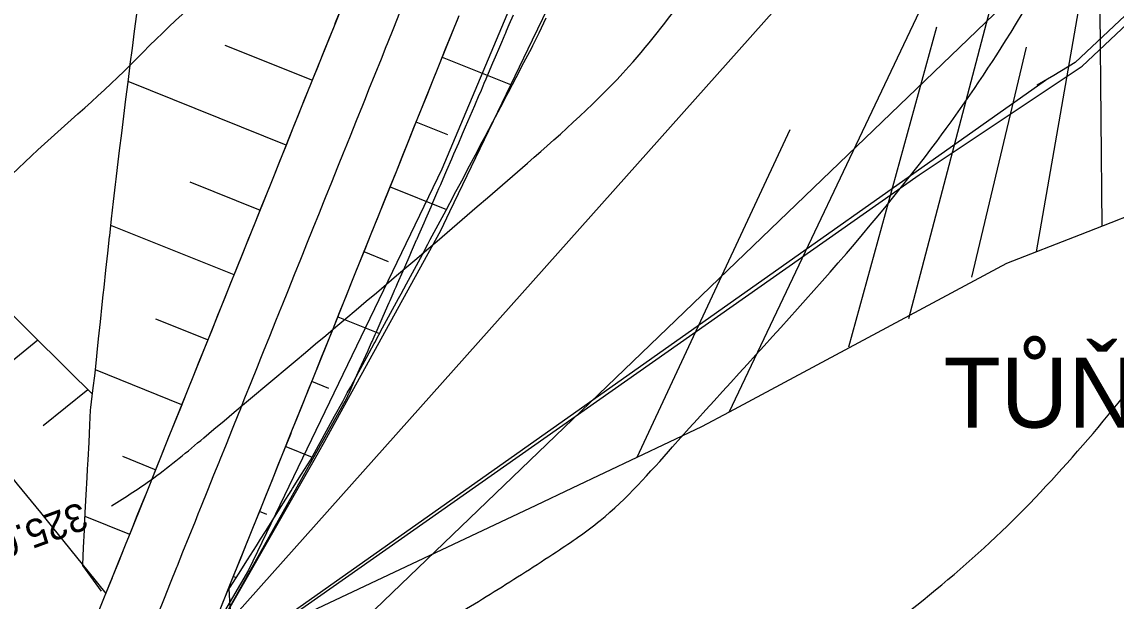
# Model space of a CAD drawing. Extents: x -564037 to -563827, y -1163561 to -1163412.
# Drawn here: x -563980.78 to -563961.22, y -1163500.71 to -1163490.36 of the extents above; entities that cross this region are included whole.
import ezdxf

# ---------------------------------------------------------------- set-up
doc = ezdxf.new("R2010")
doc.units = 0
for name, color, linetype in [('4', 7, 'Continuous'), ('5', 7, 'Continuous'), ('Default', 7, 'Continuous'), ('Line', 7, 'Continuous'), ('Vrstva 24', 7, 'Continuous'), ('Vrstva 25', 7, 'Continuous'), ('Vrstva 26', 7, 'Continuous')]:
    doc.layers.add(name, color=color, linetype=linetype)

msp = doc.modelspace()

# ---------------------------------------------------------------- linework, layer by layer
msp.add_lwpolyline([(-563976.663, -1163501.462), (-563964.742, -1163493.091), (-563961.829, -1163491.15), (-563957.41, -1163486.988), (-563956.735, -1163486.627), (-563953.281, -1163481.221), (-563953.993, -1163478.343), (-563957.796, -1163470.824), (-563957.81, -1163470.439), (-563957.835, -1163469.754), (-563958.239, -1163469.063), (-563958.187, -1163468.683), (-563959.529, -1163466.077), (-563960.166, -1163464.984), (-563964.31, -1163473.527), (-563966.903, -1163478.544), (-563968.406, -1163481.669), (-563970.316, -1163485.955), (-563973.278, -1163492.988), (-563976.735, -1163500.155), (-563977.161, -1163500.889), (-563977.363, -1163501.307)], close=True)
for points in [[(-563960.591, -1163493.664), (-563961.319, -1163493.948), (-563961.866, -1163494.161), (-563963.182, -1163494.674), (-563968.138, -1163497.33), (-563968.634, -1163497.596), (-563970.944, -1163498.688), (-563971.597, -1163498.997), (-563976.56, -1163501.343), (-563977.332, -1163501.295), (-563976.988, -1163500.693), (-563975.559, -1163498.192), (-563975.396, -1163497.906), (-563973.296, -1163494.084), (-563973.133, -1163493.747), (-563971.654, -1163490.682), (-563969.513, -1163486.248), (-563968.702, -1163484.611), (-563968.142, -1163483.478), (-563966.349, -1163479.855)], [(-563979.277, -1163500.562), (-563978.932, -1163499.705), (-563978.872, -1163499.557), (-563978.558, -1163498.777), (-563978.185, -1163497.849), (-563977.812, -1163496.922), (-563977.438, -1163495.994), (-563977.065, -1163495.066), (-563976.691, -1163494.139), (-563976.318, -1163493.211), (-563975.945, -1163492.283), (-563975.571, -1163491.355), (-563975.198, -1163490.428), (-563974.825, -1163489.5)], [(-563979.678, -1163501.56), (-563979.305, -1163500.632), (-563979.277, -1163500.562), (-563979.165, -1163500.284), (-563979.164, -1163500.282), (-563979.053, -1163500.006), (-563978.942, -1163499.731), (-563978.932, -1163499.705), (-563978.832, -1163499.456), (-563978.721, -1163499.18), (-563978.61, -1163498.905), (-563978.558, -1163498.777), (-563978.499, -1163498.63), (-563978.388, -1163498.355), (-563978.277, -1163498.079), (-563978.185, -1163497.849), (-563978.167, -1163497.804), (-563978.056, -1163497.529), (-563977.945, -1163497.253), (-563977.834, -1163496.978), (-563977.812, -1163496.922), (-563977.723, -1163496.703), (-563977.613, -1163496.427), (-563977.502, -1163496.152), (-563977.438, -1163495.994), (-563977.391, -1163495.877), (-563977.28, -1163495.601), (-563977.169, -1163495.326), (-563977.065, -1163495.066), (-563977.059, -1163495.051), (-563976.948, -1163494.775), (-563976.837, -1163494.5), (-563976.726, -1163494.225), (-563976.691, -1163494.139), (-563976.615, -1163493.949), (-563976.505, -1163493.674), (-563976.394, -1163493.399), (-563976.318, -1163493.211), (-563976.283, -1163493.123), (-563976.172, -1163492.848), (-563976.061, -1163492.573), (-563975.95, -1163492.297), (-563975.945, -1163492.283), (-563975.84, -1163492.022), (-563975.729, -1163491.747), (-563975.618, -1163491.471), (-563975.571, -1163491.355), (-563975.507, -1163491.196), (-563975.396, -1163490.921), (-563975.286, -1163490.645), (-563975.198, -1163490.428), (-563975.175, -1163490.37), (-563975.064, -1163490.095)], [(-563979.359, -1163500.529), (-563979.695, -1163500.07), (-563979.695, -1163500.068), (-563979.682, -1163499.753), (-563979.667, -1163499.439), (-563979.666, -1163499.409), (-563979.652, -1163499.126), (-563979.635, -1163498.812), (-563979.619, -1163498.499), (-563979.611, -1163498.353), (-563979.602, -1163498.186), (-563979.584, -1163497.873), (-563979.571, -1163497.559), (-563979.558, -1163497.297), (-563979.551, -1163497.247), (-563979.514, -1163496.942), (-563979.476, -1163496.637), (-563979.444, -1163496.33), (-563979.438, -1163496.267), (-563979.413, -1163496.023), (-563979.381, -1163495.716), (-563979.348, -1163495.409), (-563979.33, -1163495.233), (-563979.316, -1163495.102), (-563979.282, -1163494.796), (-563979.248, -1163494.489), (-563979.216, -1163494.2), (-563979.214, -1163494.183), (-563979.18, -1163493.877), (-563979.145, -1163493.571), (-563979.109, -1163493.266), (-563979.098, -1163493.17), (-563979.073, -1163492.96), (-563979.037, -1163492.655), (-563979, -1163492.35), (-563978.975, -1163492.142), (-563978.963, -1163492.045), (-563978.925, -1163491.74), (-563978.887, -1163491.435), (-563978.848, -1163491.131), (-563978.846, -1163491.115), (-563978.809, -1163490.827), (-563978.77, -1163490.523), (-563978.73, -1163490.219)], [(-563979.359, -1163500.529), (-563979.695, -1163500.07), (-563979.695, -1163500.068), (-563979.682, -1163499.753), (-563979.667, -1163499.439), (-563979.666, -1163499.409), (-563979.652, -1163499.126), (-563979.635, -1163498.812), (-563979.619, -1163498.499), (-563979.611, -1163498.353), (-563979.602, -1163498.186), (-563979.584, -1163497.873), (-563979.571, -1163497.559), (-563979.558, -1163497.297), (-563979.551, -1163497.247), (-563979.514, -1163496.942), (-563979.476, -1163496.637), (-563979.444, -1163496.33), (-563979.438, -1163496.267), (-563979.413, -1163496.023), (-563979.381, -1163495.716), (-563979.348, -1163495.409), (-563979.33, -1163495.233), (-563979.316, -1163495.102), (-563979.282, -1163494.796), (-563979.248, -1163494.489), (-563979.216, -1163494.2), (-563979.214, -1163494.183), (-563979.18, -1163493.877), (-563979.145, -1163493.571), (-563979.109, -1163493.266), (-563979.098, -1163493.17), (-563979.073, -1163492.96), (-563979.037, -1163492.655), (-563979, -1163492.35), (-563978.975, -1163492.142), (-563978.963, -1163492.045), (-563978.925, -1163491.74), (-563978.887, -1163491.435), (-563978.848, -1163491.131), (-563978.846, -1163491.115), (-563978.809, -1163490.827), (-563978.77, -1163490.523), (-563978.73, -1163490.219)], [(-563978.349, -1163500.935), (-563978.237, -1163500.657), (-563978.236, -1163500.655), (-563978.125, -1163500.38), (-563978.015, -1163500.104), (-563978.004, -1163500.078), (-563977.904, -1163499.829), (-563977.793, -1163499.554), (-563977.682, -1163499.279), (-563977.631, -1163499.15), (-563977.571, -1163499.003), (-563977.461, -1163498.728), (-563977.35, -1163498.453), (-563977.257, -1163498.223), (-563977.239, -1163498.177), (-563977.128, -1163497.902), (-563977.017, -1163497.627), (-563976.907, -1163497.351), (-563976.884, -1163497.295), (-563976.796, -1163497.076), (-563976.685, -1163496.801), (-563976.574, -1163496.525), (-563976.511, -1163496.367), (-563976.463, -1163496.25), (-563976.353, -1163495.975), (-563976.242, -1163495.699), (-563976.137, -1163495.44), (-563976.131, -1163495.424), (-563976.02, -1163495.149), (-563975.909, -1163494.873), (-563975.798, -1163494.598), (-563975.764, -1163494.512), (-563975.688, -1163494.323), (-563975.577, -1163494.047), (-563975.466, -1163493.772), (-563975.39, -1163493.584), (-563975.355, -1163493.497), (-563975.244, -1163493.221), (-563975.134, -1163492.946), (-563975.023, -1163492.671), (-563975.017, -1163492.657), (-563974.912, -1163492.395), (-563974.801, -1163492.12), (-563974.69, -1163491.845), (-563974.644, -1163491.729), (-563974.58, -1163491.569), (-563974.469, -1163491.294), (-563974.358, -1163491.019), (-563974.27, -1163490.801), (-563974.247, -1163490.744), (-563974.136, -1163490.468), (-563974.025, -1163490.193)], [(-563977.421, -1163501.309), (-563977.076, -1163500.451), (-563977.017, -1163500.304), (-563976.703, -1163499.524), (-563976.33, -1163498.596), (-563975.956, -1163497.668), (-563975.583, -1163496.741), (-563975.209, -1163495.813), (-563974.836, -1163494.885), (-563974.463, -1163493.958), (-563974.089, -1163493.03), (-563973.716, -1163492.102), (-563973.343, -1163491.175), (-563972.969, -1163490.247)], [(-563977.198, -1163500.753), (-563977.087, -1163500.478), (-563977.076, -1163500.451), (-563976.976, -1163500.203), (-563976.865, -1163499.927), (-563976.755, -1163499.652), (-563976.703, -1163499.524), (-563976.644, -1163499.377), (-563976.533, -1163499.101), (-563976.422, -1163498.826), (-563976.33, -1163498.596), (-563976.311, -1163498.551), (-563976.201, -1163498.275), (-563976.09, -1163498), (-563975.979, -1163497.725), (-563975.956, -1163497.668), (-563975.868, -1163497.449), (-563975.757, -1163497.174), (-563975.646, -1163496.899), (-563975.583, -1163496.741), (-563975.536, -1163496.623), (-563975.425, -1163496.348), (-563975.314, -1163496.073), (-563975.209, -1163495.813), (-563975.203, -1163495.797), (-563975.092, -1163495.522), (-563974.982, -1163495.247), (-563974.871, -1163494.971), (-563974.836, -1163494.885), (-563974.76, -1163494.696), (-563974.649, -1163494.421), (-563974.538, -1163494.145), (-563974.463, -1163493.958), (-563974.428, -1163493.87), (-563974.317, -1163493.595), (-563974.206, -1163493.319), (-563974.095, -1163493.044), (-563974.089, -1163493.03), (-563973.984, -1163492.769), (-563973.873, -1163492.493), (-563973.763, -1163492.218), (-563973.716, -1163492.102), (-563973.652, -1163491.943), (-563973.541, -1163491.668), (-563973.43, -1163491.392), (-563973.343, -1163491.175), (-563973.319, -1163491.117), (-563973.209, -1163490.842), (-563973.098, -1163490.566), (-563972.987, -1163490.291)], [(-563977.077, -1163500.482), (-563977.061, -1163500.458), (-563976.914, -1163500.227), (-563976.753, -1163499.973), (-563976.591, -1163499.718), (-563976.516, -1163499.599), (-563976.429, -1163499.463), (-563976.268, -1163499.208), (-563976.107, -1163498.953), (-563975.973, -1163498.74), (-563975.946, -1163498.698), (-563975.785, -1163498.442), (-563975.625, -1163498.187), (-563975.48, -1163497.925), (-563975.451, -1163497.872), (-563975.336, -1163497.663), (-563975.193, -1163497.401), (-563975.049, -1163497.139), (-563974.967, -1163496.989), (-563974.906, -1163496.877), (-563974.763, -1163496.614), (-563974.62, -1163496.352), (-563974.485, -1163496.104), (-563974.477, -1163496.09), (-563974.335, -1163495.827), (-563974.192, -1163495.564), (-563974.05, -1163495.302), (-563974.006, -1163495.219), (-563973.909, -1163495.039), (-563973.767, -1163494.776), (-563973.625, -1163494.513), (-563973.529, -1163494.333), (-563973.484, -1163494.25), (-563973.343, -1163493.987), (-563973.202, -1163493.723), (-563973.062, -1163493.46), (-563973.055, -1163493.446), (-563972.922, -1163493.196), (-563972.782, -1163492.933), (-563972.642, -1163492.669), (-563972.583, -1163492.558), (-563972.502, -1163492.405), (-563972.363, -1163492.142), (-563972.224, -1163491.878), (-563972.114, -1163491.669), (-563972.085, -1163491.614), (-563971.946, -1163491.35), (-563971.808, -1163491.085), (-563971.669, -1163490.821), (-563971.647, -1163490.779), (-563971.537, -1163490.555), (-563971.41, -1163490.286)], [(-563977.077, -1163500.482), (-563977.061, -1163500.458), (-563976.914, -1163500.227), (-563976.753, -1163499.973), (-563976.591, -1163499.718), (-563976.516, -1163499.599), (-563976.429, -1163499.463), (-563976.268, -1163499.208), (-563976.107, -1163498.953), (-563975.973, -1163498.74), (-563975.946, -1163498.698), (-563975.785, -1163498.442), (-563975.625, -1163498.187), (-563975.48, -1163497.925), (-563975.451, -1163497.872), (-563975.336, -1163497.663), (-563975.193, -1163497.401), (-563975.049, -1163497.139), (-563974.967, -1163496.989), (-563974.906, -1163496.877), (-563974.763, -1163496.614), (-563974.62, -1163496.352), (-563974.485, -1163496.104), (-563974.477, -1163496.09), (-563974.335, -1163495.827), (-563974.192, -1163495.564), (-563974.05, -1163495.302), (-563974.006, -1163495.219), (-563973.909, -1163495.039), (-563973.767, -1163494.776), (-563973.625, -1163494.513), (-563973.529, -1163494.333), (-563973.484, -1163494.25), (-563973.343, -1163493.987), (-563973.202, -1163493.723), (-563973.062, -1163493.46), (-563973.055, -1163493.446), (-563972.922, -1163493.196), (-563972.782, -1163492.933), (-563972.642, -1163492.669), (-563972.583, -1163492.558), (-563972.502, -1163492.405), (-563972.363, -1163492.142), (-563972.224, -1163491.878), (-563972.114, -1163491.669), (-563972.085, -1163491.614), (-563971.946, -1163491.35), (-563971.808, -1163491.085), (-563971.669, -1163490.821), (-563971.647, -1163490.779), (-563971.537, -1163490.555), (-563971.41, -1163490.286)], [(-563986.706, -1163491.418), (-563986.045, -1163492.234), (-563985.906, -1163492.405), (-563985.276, -1163493.181), (-563985.14, -1163493.35), (-563984.646, -1163493.958), (-563984.016, -1163494.734), (-563983.386, -1163495.511), (-563982.756, -1163496.288), (-563982.126, -1163497.064), (-563981.496, -1163497.841), (-563980.866, -1163498.617), (-563980.454, -1163499.125), (-563980.236, -1163499.394), (-563979.606, -1163500.17), (-563979.281, -1163500.571)], [(-563984.543, -1163491.913), (-563984.084, -1163492.493), (-563983.524, -1163493.048), (-563982.81, -1163493.756), (-563982.095, -1163494.463), (-563981.38, -1163495.171), (-563980.665, -1163495.879), (-563979.951, -1163496.587), (-563979.523, -1163497.011)], [(-563979.198, -1163507.467), (-563978.368, -1163507.477), (-563975.597, -1163507.515), (-563975.386, -1163507.517), (-563975.87, -1163506.327), (-563976.036, -1163505.182), (-563976.046, -1163504.1), (-563976.056, -1163503.018), (-563976.088, -1163501.927), (-563976.1, -1163501.84), (-563976.996, -1163501.156), (-563976.997, -1163501.154), (-563977.062, -1163500.808), (-563977.077, -1163500.482)], [(-563979.198, -1163507.467), (-563978.368, -1163507.477), (-563975.597, -1163507.515), (-563975.386, -1163507.517), (-563975.87, -1163506.327), (-563976.036, -1163505.182), (-563976.046, -1163504.1), (-563976.056, -1163503.018), (-563976.088, -1163501.927), (-563976.1, -1163501.84), (-563976.996, -1163501.156), (-563976.997, -1163501.154), (-563977.062, -1163500.808), (-563977.077, -1163500.482)]]:
    msp.add_lwpolyline(points)
at = {"layer": '5'}
msp.add_line((-563974.94, -1163501.303), (-563959.546, -1163486.507), dxfattribs=at)
at = {"layer": 'Default'}
for points in [[(-563957.497, -1163486.891), (-563961.953, -1163491.085), (-563962.333, -1163491.316), (-563962.631, -1163491.492), (-563962.482, -1163491.404), (-563976.56, -1163501.343)], [(-563977.332, -1163501.295), (-563974.976, -1163497.082), (-563974.974, -1163497.079), (-563974.939, -1163497), (-563974.935, -1163496.992), (-563974.849, -1163496.797), (-563974.841, -1163496.78), (-563974.722, -1163496.513), (-563974.711, -1163496.488), (-563974.596, -1163496.229), (-563974.589, -1163496.212), (-563974.532, -1163496.085), (-563974.525, -1163496.068), (-563974.47, -1163495.944), (-563974.453, -1163495.906), (-563974.344, -1163495.659), (-563974.324, -1163495.615), (-563974.218, -1163495.374), (-563974.203, -1163495.339), (-563974.128, -1163495.17), (-563974.122, -1163495.155), (-563974.093, -1163495.09), (-563974.069, -1163495.034), (-563973.968, -1163494.805), (-563973.941, -1163494.744), (-563973.843, -1163494.52), (-563973.816, -1163494.459), (-563973.727, -1163494.254), (-563973.725, -1163494.249), (-563973.718, -1163494.234), (-563973.688, -1163494.165), (-563973.594, -1163493.949), (-563973.562, -1163493.876), (-563973.47, -1163493.664), (-563973.436, -1163493.586), (-563973.346, -1163493.378), (-563973.341, -1163493.366), (-563973.328, -1163493.337), (-563973.297, -1163493.267), (-563973.222, -1163493.093), (-563973.185, -1163493.008), (-563973.099, -1163492.807), (-563973.061, -1163492.719), (-563972.975, -1163492.522), (-563972.961, -1163492.488), (-563972.931, -1163492.418), (-563972.905, -1163492.359), (-563972.852, -1163492.236), (-563972.812, -1163492.141), (-563972.729, -1163491.95), (-563972.688, -1163491.852), (-563972.607, -1163491.664), (-563972.582, -1163491.606), (-563972.536, -1163491.499), (-563972.518, -1163491.456), (-563972.485, -1163491.378), (-563972.441, -1163491.275), (-563972.363, -1163491.092), (-563972.318, -1163490.986), (-563972.241, -1163490.805), (-563972.204, -1163490.719), (-563972.145, -1163490.579), (-563972.135, -1163490.556), (-563972.119, -1163490.519), (-563972.072, -1163490.408), (-563971.998, -1163490.232)]]:
    msp.add_lwpolyline(points, dxfattribs=at)
at = {"layer": 'Line'}
for p, q in [((-563962.901, -1163485.181), (-563977.279, -1163501.298)), ((-563964.928, -1163495.656), (-563962.285, -1163485.606)), ((-563968.138, -1163497.33), (-563962.69, -1163485.858)), ((-563962.645, -1163494.465), (-563961.176, -1163486.037)), ((-563961.513, -1163490.172), (-563961.48, -1163494.011)), ((-563964.431, -1163490.456), (-563966.005, -1163496.172)), ((-563977.155, -1163490.772), (-563975.59, -1163491.402)), ((-563962.83, -1163490.808), (-563963.81, -1163494.918)), ((-563973.268, -1163490.989), (-563972.021, -1163491.491)), ((-563976.057, -1163492.562), (-563978.885, -1163491.423)), ((-563973.171, -1163492.376), (-563973.735, -1163492.149)), ((-563967.053, -1163492.285), (-563969.789, -1163498.142)), ((-563977.783, -1163493.214), (-563976.523, -1163493.721)), ((-563974.201, -1163493.308), (-563973.196, -1163493.713)), ((-563976.99, -1163494.881), (-563979.193, -1163493.994)), ((-563974.23, -1163494.644), (-563974.668, -1163494.468)), ((-563978.396, -1163495.662), (-563977.457, -1163496.04)), ((-563975.135, -1163495.627), (-563974.389, -1163495.928)), ((-563981.981, -1163497.243), (-563980.501, -1163496.042)), ((-563977.924, -1163497.2), (-563979.47, -1163496.578)), ((-563975.296, -1163496.91), (-563975.602, -1163496.787)), ((-563980.401, -1163497.57), (-563979.608, -1163496.927)), ((-563976.068, -1163497.947), (-563975.597, -1163498.136)), ((-563978.988, -1163498.119), (-563978.39, -1163498.36)), ((-563976.403, -1163499.159), (-563976.535, -1163499.106)), ((-563978.857, -1163499.519), (-563979.655, -1163499.198)), ((-563977.002, -1163500.266), (-563976.952, -1163500.286))]:
    msp.add_line(p, q, dxfattribs=at)
at = {"layer": 'Vrstva 24'}
for points in [[(-563987.107, -1163486.915), (-563987.454, -1163489.613), (-563987.517, -1163490.15), (-563987.54, -1163490.422), (-563987.53, -1163490.559), (-563987.493, -1163490.695), (-563987.417, -1163490.784), (-563987.298, -1163490.832), (-563987.065, -1163490.801), (-563986.897, -1163490.636), (-563986.866, -1163490.616), (-563986.653, -1163490.561), (-563986.65, -1163490.24), (-563986.645, -1163490.2), (-563986.382, -1163489.381), (-563986.092, -1163488.576), (-563985.799, -1163487.775), (-563985.528, -1163486.967), (-563985.38, -1163486.476), (-563984.961, -1163484.997), (-563984.678, -1163484.011), (-563984.372, -1163483.032), (-563984.225, -1163482.649), (-563983.962, -1163482.075), (-563983.672, -1163481.512), (-563983.189, -1163480.348), (-563983.119, -1163479.959), (-563982.881, -1163478.598), (-563982.738, -1163477.921), (-563982.65, -1163477.583), (-563982.6, -1163477.415), (-563982.546, -1163477.247), (-563982.332, -1163477.109), (-563982.215, -1163477.074), (-563982.092, -1163477.059), (-563981.971, -1163477.035), (-563981.858, -1163476.974), (-563981.222, -1163476.317), (-563980.763, -1163475.576), (-563980.303, -1163473.933), (-563980.283, -1163473.505), (-563980.299, -1163473.076), (-563980.318, -1163472.648), (-563980.308, -1163472.221), (-563980.208, -1163471.241), (-563979.978, -1163470.27), (-563979.506, -1163469.655), (-563979.053, -1163469.383), (-563978.331, -1163469.068), (-563977.756, -1163469.029), (-563977.053, -1163469.053), (-563976.495, -1163468.977), (-563976.227, -1163468.861), (-563976.095, -1163468.775), (-563975.963, -1163468.666), (-563975.645, -1163468.239), (-563975.569, -1163468.015), (-563975.54, -1163467.788), (-563975.712, -1163467.263), (-563975.92, -1163467.014), (-563976.134, -1163466.799), (-563976.603, -1163466.431), (-563977.767, -1163465.694), (-563978.114, -1163465.416), (-563978.319, -1163465.046), (-563978.354, -1163464.593), (-563978.366, -1163464.139), (-563978.374, -1163463.685), (-563978.396, -1163463.232), (-563978.403, -1163463.165), (-563978.508, -1163462.771), (-563978.665, -1163462.394), (-563979.088, -1163461.691), (-563979.473, -1163461.171), (-563980.119, -1163460.346)], [(-563978.297, -1163509.021), (-563978.261, -1163509.003), (-563973.613, -1163506.565), (-563973.263, -1163506.351), (-563972.852, -1163506.074), (-563964.784, -1163500.778), (-563963.064, -1163499.262), (-563960.133, -1163495.845), (-563958.857, -1163494.133), (-563956.661, -1163490.461), (-563954.703, -1163486.917), (-563951.017, -1163480.396), (-563950.659, -1163479.782), (-563950.563, -1163479.619)], [(-563978.949, -1163516.619), (-563975.171, -1163515.313), (-563974.108, -1163514.884), (-563972.002, -1163513.885), (-563969.907, -1163512.865), (-563967.813, -1163511.846), (-563965.709, -1163510.847), (-563964.325, -1163510.207), (-563962.597, -1163509.381), (-563961.075, -1163508.613), (-563959.57, -1163507.812), (-563958.075, -1163506.99), (-563956.583, -1163506.159), (-563955.558, -1163505.578), (-563954.547, -1163504.976), (-563953.555, -1163504.342), (-563952.588, -1163503.665), (-563951.319, -1163502.66), (-563950.112, -1163501.587), (-563949.038, -1163500.583), (-563947.98, -1163499.563), (-563946.918, -1163498.547), (-563945.835, -1163497.554), (-563945.703, -1163497.443), (-563945.609, -1163497.371), (-563945.171, -1163496.955), (-563943.72, -1163495.5)]]:
    msp.add_spline(points, degree=3, dxfattribs=at)
at = {"layer": 'Vrstva 25'}
msp.add_spline([(-563979.181, -1163499.008), (-563978.428, -1163498.506), (-563977.533, -1163497.79), (-563971.745, -1163492.882), (-563969.933, -1163491.157), (-563968.824, -1163489.747), (-563966.163, -1163485.494), (-563965.399, -1163484.181), (-563964.1, -1163481.868), (-563961.431, -1163477.021), (-563960.731, -1163475.725), (-563960.044, -1163474.189), (-563959.617, -1163472.641), (-563959.116, -1163469.866), (-563959.228, -1163469.046), (-563959.512, -1163468.326), (-563959.82, -1163467.638), (-563960.515, -1163466.313), (-563961.208, -1163465.1)], degree=3, dxfattribs=at)
at = {"layer": 'Vrstva 26'}
for points in [[(-563980.746, -1163506.255), (-563980.047, -1163505.928), (-563978.898, -1163505.186), (-563978.091, -1163504.559), (-563977.304, -1163503.908), (-563976.514, -1163503.264), (-563975.695, -1163502.656), (-563974.591, -1163501.929), (-563973.468, -1163501.232), (-563972.341, -1163500.538), (-563971.226, -1163499.825), (-563970.447, -1163499.268), (-563969.15, -1163497.951), (-563964.517, -1163492.611), (-563963.2, -1163490.7), (-563960.284, -1163485.41), (-563958.779, -1163482.786), (-563956.142, -1163478.307), (-563954.428, -1163475.228)], [(-563991.611, -1163485.501), (-563991.561, -1163485.341), (-563991.21, -1163484.328), (-563991.006, -1163483.823), (-563990.782, -1163483.317), (-563990.669, -1163483.212), (-563989.835, -1163483.385), (-563989.335, -1163483.591), (-563988.852, -1163483.806), (-563988.416, -1163484.095), (-563988.226, -1163484.288), (-563988.06, -1163484.524), (-563987.844, -1163485.266), (-563987.9, -1163486.009), (-563988.137, -1163487.627), (-563988.511, -1163490.277), (-563988.935, -1163493.479), (-563989.128, -1163493.944), (-563989.201, -1163494.071), (-563989.25, -1163494.355), (-563988.964, -1163494.223), (-563988.759, -1163494.176), (-563988.506, -1163494.004), (-563988.295, -1163493.783), (-563987.947, -1163493.254), (-563987.614, -1163492.703), (-563987.194, -1163492.246), (-563986.965, -1163492.108), (-563986.555, -1163492.017), (-563986.094, -1163492.011), (-563985.68, -1163491.951), (-563985.522, -1163491.857), (-563985.413, -1163491.697), (-563985.286, -1163491.116), (-563985.31, -1163490.532), (-563985.383, -1163489.947), (-563985.403, -1163489.364), (-563985.38, -1163489.09), (-563984.85, -1163487.266), (-563984.13, -1163485.089), (-563983.855, -1163484.492), (-563982.893, -1163482.465), (-563982.427, -1163481.437), (-563982.206, -1163480.907), (-563982.1, -1163480.637), (-563981.997, -1163480.363), (-563981.967, -1163480.031), (-563981.995, -1163479.694), (-563982.002, -1163479.122), (-563981.99, -1163478.836), (-563981.972, -1163478.693), (-563981.942, -1163478.551), (-563981.849, -1163478.489), (-563981.662, -1163478.435), (-563981.467, -1163478.411), (-563981.273, -1163478.37), (-563981.089, -1163478.263), (-563980.515, -1163477.708), (-563980.017, -1163477.13), (-563979.334, -1163476.087)], [(-564001.195, -1163498.271), (-563999.625, -1163497.54), (-563999.32, -1163497.49), (-563999.014, -1163497.455), (-563998.404, -1163497.374), (-563997.456, -1163497.19), (-563996.983, -1163497.106), (-563996.746, -1163497.08), (-563996.628, -1163497.073), (-563996.51, -1163497.07), (-563996.001, -1163497.405), (-563995.843, -1163497.69), (-563995.811, -1163497.929), (-563995.865, -1163498.008), (-563995.966, -1163498.084), (-563996.177, -1163498.245), (-563996.314, -1163498.396), (-563996.473, -1163498.559), (-563996.786, -1163498.911), (-563996.954, -1163499.618), (-563996.725, -1163499.926), (-563996.435, -1163500.208), (-563996.113, -1163500.428), (-563995.791, -1163500.55), (-563995.579, -1163500.527), (-563995.362, -1163500.405), (-563995.147, -1163500.225), (-563994.94, -1163500.032), (-563994.454, -1163499.316), (-563994.189, -1163498.497), (-563993.911, -1163497.703), (-563993.694, -1163497.356), (-563993.385, -1163497.063), (-563993.106, -1163496.925), (-563992.801, -1163496.863), (-563992.211, -1163496.877), (-563991.901, -1163497.039), (-563991.591, -1163497.33), (-563991.287, -1163497.564), (-563990.995, -1163497.556), (-563990.269, -1163497.037), (-563989.554, -1163496.504), (-563988.84, -1163495.969), (-563988.119, -1163495.444), (-563987.86, -1163495.24), (-563987.725, -1163495.146), (-563987.573, -1163495.071), (-563987.369, -1163495.063), (-563987.165, -1163495.092), (-563986.561, -1163495.087), (-563985.951, -1163495.108), (-563984.727, -1163495.135), (-563983.531, -1163494.982), (-563982.954, -1163494.778), (-563982.673, -1163494.634), (-563982.398, -1163494.458), (-563981.989, -1163494.127), (-563981.638, -1163493.78), (-563980.962, -1163493.086), (-563979.072, -1163491.35), (-563977.168, -1163489.628), (-563976.69, -1163489.292), (-563976.196, -1163488.717), (-563974.229, -1163486.225)], [(-563979.339, -1163513.451), (-563976.454, -1163512.115), (-563974.079, -1163510.944), (-563968.189, -1163507.943), (-563964.488, -1163505.88), (-563958.479, -1163502.145), (-563957, -1163500.857), (-563954.437, -1163497.718), (-563953.277, -1163496.363), (-563952.789, -1163495.73), (-563951.998, -1163494.583), (-563951.243, -1163493.409), (-563950.48, -1163492.242), (-563949.665, -1163491.113), (-563947.525, -1163488.408), (-563947.448, -1163488.312)]]:
    msp.add_spline(points, degree=3, dxfattribs=at)

# ---------------------------------------------------------------- texts
at = {"layer": '4'}
msp.add_text('TŮŇ T1', height=1.25, rotation=360, dxfattribs=at).set_placement((-563964.304, -1163497.609))
at = {"layer": 'Vrstva 25'}
msp.add_text('325.00', height=0.5, rotation=200.0822, dxfattribs=at).set_placement((-563979.73, -1163498.929))

doc.saveas('drawing.dxf')
